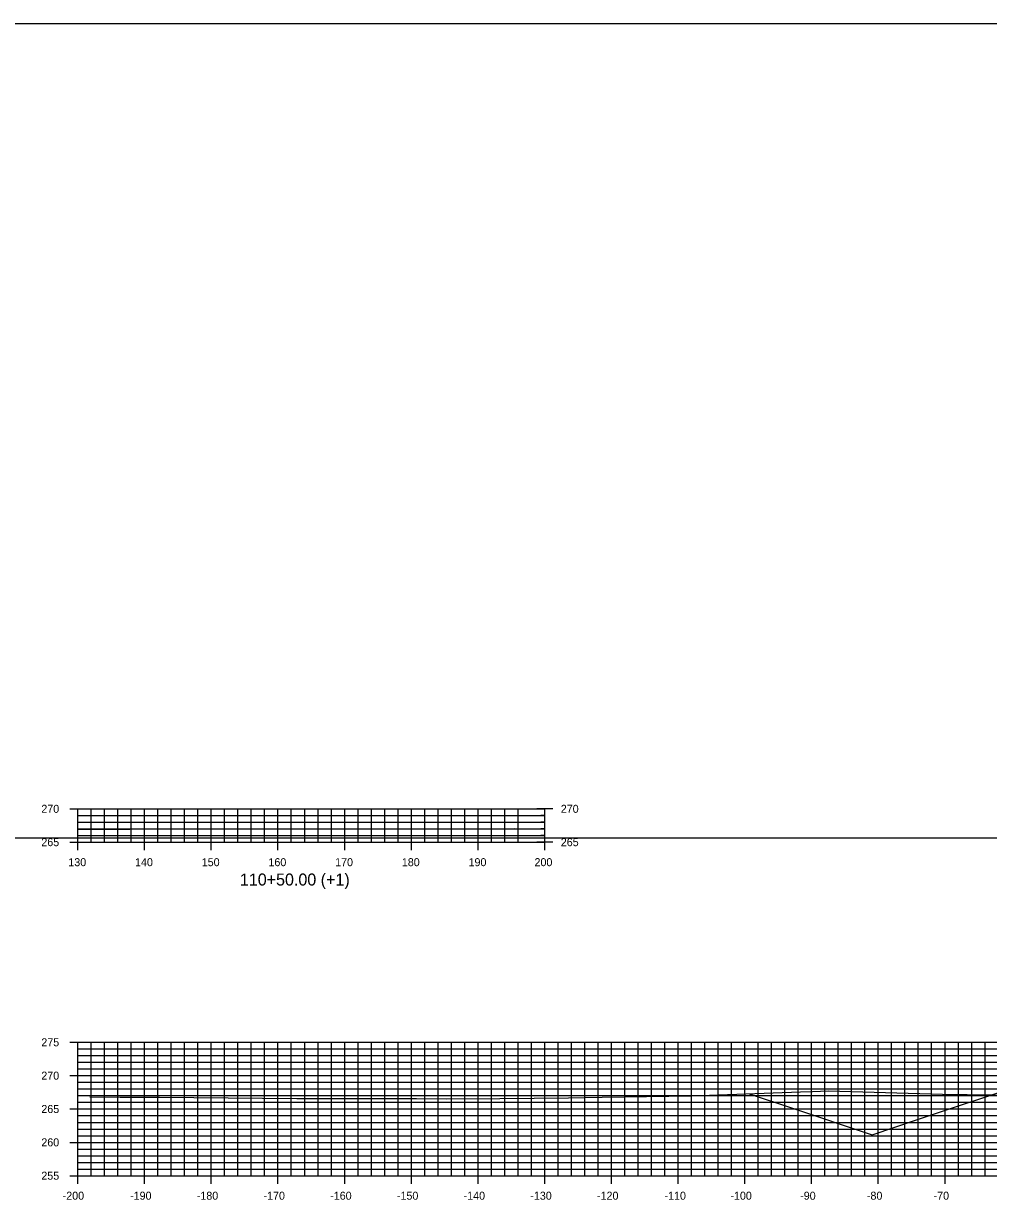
# Model space of a CAD drawing. Extents: x 1661012 to 1662122, y 670053 to 671852.
# Drawn here: x 1661778.9 to 1661923.5, y 671675 to 671852.4 of the extents above; entities that cross this region are included whole.
import ezdxf

# ---------------------------------------------------------------- set-up
doc = ezdxf.new("R2010")
doc.units = 0
for name, color, linetype in [('R_Concrete', 7, 'Continuous'), ('R_Concrete Hidden', 7, 'Continuous'), ('R_Erosion', 7, 'Continuous'), ('R_Exist Surface', 7, 'Continuous'), ('R_Proposed Road', 7, 'Continuous'), ('R_ROW Annot', 7, 'Continuous')]:
    doc.layers.add(name, color=color, linetype=linetype)

msp = doc.modelspace()

# ---------------------------------------------------------------- linework, layer by layer
at = {"layer": 'R_Concrete'}
for p, q in [((1661785.79, 671734.7), (1661788.19, 671734.7)), ((1661786.99, 671734.7), (1661856.99, 671734.7)), ((1661786.99, 671729.7), (1661786.99, 671734.7)), ((1661786.99, 671729.7), (1661786.99, 671734.7)), ((1661786.99, 671729.7), (1661786.99, 671734.7)), ((1661788.99, 671729.7), (1661788.99, 671734.7)), ((1661790.99, 671729.7), (1661790.99, 671734.7)), ((1661792.99, 671729.7), (1661792.99, 671734.7)), ((1661794.99, 671729.7), (1661794.99, 671734.7)), ((1661796.99, 671729.7), (1661796.99, 671734.7)), ((1661798.99, 671729.7), (1661798.99, 671734.7)), ((1661800.99, 671729.7), (1661800.99, 671734.7)), ((1661802.99, 671729.7), (1661802.99, 671734.7)), ((1661804.99, 671729.7), (1661804.99, 671734.7)), ((1661806.99, 671729.7), (1661806.99, 671734.7)), ((1661808.99, 671729.7), (1661808.99, 671734.7)), ((1661810.99, 671729.7), (1661810.99, 671734.7)), ((1661812.99, 671729.7), (1661812.99, 671734.7)), ((1661814.99, 671729.7), (1661814.99, 671734.7)), ((1661816.99, 671729.7), (1661816.99, 671734.7)), ((1661818.99, 671729.7), (1661818.99, 671734.7)), ((1661820.99, 671729.7), (1661820.99, 671734.7)), ((1661822.99, 671729.7), (1661822.99, 671734.7)), ((1661824.99, 671729.7), (1661824.99, 671734.7)), ((1661826.99, 671729.7), (1661826.99, 671734.7)), ((1661828.99, 671729.7), (1661828.99, 671734.7)), ((1661830.99, 671729.7), (1661830.99, 671734.7)), ((1661832.99, 671729.7), (1661832.99, 671734.7)), ((1661834.99, 671729.7), (1661834.99, 671734.7)), ((1661836.99, 671729.7), (1661836.99, 671734.7)), ((1661838.99, 671729.7), (1661838.99, 671734.7)), ((1661840.99, 671729.7), (1661840.99, 671734.7)), ((1661842.99, 671729.7), (1661842.99, 671734.7)), ((1661844.99, 671729.7), (1661844.99, 671734.7)), ((1661846.99, 671729.7), (1661846.99, 671734.7)), ((1661848.99, 671729.7), (1661848.99, 671734.7)), ((1661850.99, 671729.7), (1661850.99, 671734.7)), ((1661852.99, 671729.7), (1661852.99, 671734.7)), ((1661858.19, 671734.7), (1661855.79, 671734.7)), ((1661856.99, 671729.7), (1661856.99, 671734.7)), ((1661856.99, 671729.7), (1661856.99, 671734.7)), ((1661786.99, 671733.7), (1661856.99, 671733.7)), ((1661786.99, 671733.7), (1661787.59, 671733.7)), ((1661786.99, 671732.7), (1661856.99, 671732.7)), ((1661786.99, 671732.7), (1661787.59, 671732.7)), ((1661856.99, 671733.7), (1661856.39, 671733.7)), ((1661856.99, 671732.7), (1661856.39, 671732.7)), ((1661786.99, 671731.7), (1661856.99, 671731.7)), ((1661786.99, 671731.7), (1661787.59, 671731.7)), ((1661786.99, 671728.5), (1661786.99, 671730.9)), ((1661786.99, 671728.5), (1661786.99, 671730.9)), ((1661796.99, 671728.5), (1661796.99, 671730.9)), ((1661806.99, 671728.5), (1661806.99, 671730.9)), ((1661816.99, 671728.5), (1661816.99, 671730.9)), ((1661826.99, 671728.5), (1661826.99, 671730.9)), ((1661836.99, 671728.5), (1661836.99, 671730.9)), ((1661846.99, 671728.5), (1661846.99, 671730.9)), ((1661856.99, 671731.7), (1661856.39, 671731.7)), ((1661856.99, 671728.5), (1661856.99, 671730.9)), ((1661785.79, 671729.7), (1661788.19, 671729.7)), ((1661786.99, 671730.7), (1661856.99, 671730.7)), ((1661786.99, 671730.7), (1661787.59, 671730.7)), ((1661786.99, 671729.7), (1661786.99, 671730.3)), ((1661786.99, 671729.7), (1661856.99, 671729.7)), ((1661788.99, 671729.7), (1661788.99, 671730.3)), ((1661790.99, 671729.7), (1661790.99, 671730.3)), ((1661792.99, 671729.7), (1661792.99, 671730.3)), ((1661794.99, 671729.7), (1661794.99, 671730.3)), ((1661798.99, 671729.7), (1661798.99, 671730.3)), ((1661800.99, 671729.7), (1661800.99, 671730.3)), ((1661802.99, 671729.7), (1661802.99, 671730.3)), ((1661804.99, 671729.7), (1661804.99, 671730.3)), ((1661808.99, 671729.7), (1661808.99, 671730.3)), ((1661810.99, 671729.7), (1661810.99, 671730.3)), ((1661812.99, 671729.7), (1661812.99, 671730.3)), ((1661814.99, 671729.7), (1661814.99, 671730.3)), ((1661818.99, 671729.7), (1661818.99, 671730.3)), ((1661820.99, 671729.7), (1661820.99, 671730.3)), ((1661822.99, 671729.7), (1661822.99, 671730.3)), ((1661824.99, 671729.7), (1661824.99, 671730.3)), ((1661828.99, 671729.7), (1661828.99, 671730.3)), ((1661830.99, 671729.7), (1661830.99, 671730.3)), ((1661832.99, 671729.7), (1661832.99, 671730.3)), ((1661834.99, 671729.7), (1661834.99, 671730.3)), ((1661838.99, 671729.7), (1661838.99, 671730.3)), ((1661840.99, 671729.7), (1661840.99, 671730.3)), ((1661842.99, 671729.7), (1661842.99, 671730.3)), ((1661844.99, 671729.7), (1661844.99, 671730.3)), ((1661848.99, 671729.7), (1661848.99, 671730.3)), ((1661850.99, 671729.7), (1661850.99, 671730.3)), ((1661852.99, 671729.7), (1661852.99, 671730.3)), ((1661858.19, 671729.7), (1661855.79, 671729.7)), ((1661856.99, 671730.7), (1661856.39, 671730.7)), ((1661856.99, 671729.7), (1661856.99, 671730.3)), ((1661785.79, 671699.7), (1661788.19, 671699.7)), ((1661786.99, 671699.7), (1662116.99, 671699.7)), ((1661786.99, 671679.7), (1661786.99, 671699.7)), ((1661788.99, 671679.7), (1661788.99, 671699.7)), ((1661790.99, 671679.7), (1661790.99, 671699.7)), ((1661792.99, 671679.7), (1661792.99, 671699.7)), ((1661794.99, 671679.7), (1661794.99, 671699.7)), ((1661796.99, 671679.7), (1661796.99, 671699.7)), ((1661798.99, 671679.7), (1661798.99, 671699.7)), ((1661800.99, 671679.7), (1661800.99, 671699.7)), ((1661802.99, 671679.7), (1661802.99, 671699.7)), ((1661804.99, 671679.7), (1661804.99, 671699.7)), ((1661806.99, 671679.7), (1661806.99, 671699.7)), ((1661808.99, 671679.7), (1661808.99, 671699.7)), ((1661810.99, 671679.7), (1661810.99, 671699.7)), ((1661812.99, 671679.7), (1661812.99, 671699.7)), ((1661814.99, 671679.7), (1661814.99, 671699.7)), ((1661816.99, 671679.7), (1661816.99, 671699.7)), ((1661818.99, 671679.7), (1661818.99, 671699.7)), ((1661820.99, 671679.7), (1661820.99, 671699.7)), ((1661822.99, 671679.7), (1661822.99, 671699.7)), ((1661824.99, 671679.7), (1661824.99, 671699.7)), ((1661826.99, 671679.7), (1661826.99, 671699.7)), ((1661828.99, 671679.7), (1661828.99, 671699.7)), ((1661830.99, 671679.7), (1661830.99, 671699.7)), ((1661832.99, 671679.7), (1661832.99, 671699.7)), ((1661834.99, 671679.7), (1661834.99, 671699.7)), ((1661836.99, 671679.7), (1661836.99, 671699.7)), ((1661838.99, 671679.7), (1661838.99, 671699.7)), ((1661840.99, 671679.7), (1661840.99, 671699.7)), ((1661842.99, 671679.7), (1661842.99, 671699.7)), ((1661844.99, 671679.7), (1661844.99, 671699.7)), ((1661846.99, 671679.7), (1661846.99, 671699.7)), ((1661848.99, 671679.7), (1661848.99, 671699.7)), ((1661850.99, 671679.7), (1661850.99, 671699.7)), ((1661852.99, 671679.7), (1661852.99, 671699.7)), ((1661854.99, 671679.7), (1661854.99, 671699.7)), ((1661856.99, 671679.7), (1661856.99, 671699.7)), ((1661858.99, 671679.7), (1661858.99, 671699.7)), ((1661860.99, 671679.7), (1661860.99, 671699.7)), ((1661862.99, 671679.7), (1661862.99, 671699.7)), ((1661864.99, 671679.7), (1661864.99, 671699.7)), ((1661866.99, 671679.7), (1661866.99, 671699.7)), ((1661868.99, 671679.7), (1661868.99, 671699.7)), ((1661870.99, 671679.7), (1661870.99, 671699.7)), ((1661872.99, 671679.7), (1661872.99, 671699.7)), ((1661874.99, 671679.7), (1661874.99, 671699.7)), ((1661876.99, 671679.7), (1661876.99, 671699.7)), ((1661878.99, 671679.7), (1661878.99, 671699.7)), ((1661880.99, 671679.7), (1661880.99, 671699.7)), ((1661882.99, 671679.7), (1661882.99, 671699.7)), ((1661884.99, 671679.7), (1661884.99, 671699.7)), ((1661886.99, 671679.7), (1661886.99, 671699.7)), ((1661888.99, 671679.7), (1661888.99, 671699.7)), ((1661890.99, 671679.7), (1661890.99, 671699.7)), ((1661892.99, 671679.7), (1661892.99, 671699.7)), ((1661894.99, 671679.7), (1661894.99, 671699.7)), ((1661896.99, 671679.7), (1661896.99, 671699.7)), ((1661898.99, 671679.7), (1661898.99, 671699.7)), ((1661900.99, 671679.7), (1661900.99, 671699.7)), ((1661902.99, 671679.7), (1661902.99, 671699.7)), ((1661904.99, 671679.7), (1661904.99, 671699.7)), ((1661906.99, 671679.7), (1661906.99, 671699.7)), ((1661908.99, 671679.7), (1661908.99, 671699.7)), ((1661910.99, 671679.7), (1661910.99, 671699.7)), ((1661912.99, 671679.7), (1661912.99, 671699.7)), ((1661914.99, 671679.7), (1661914.99, 671699.7)), ((1661916.99, 671679.7), (1661916.99, 671699.7)), ((1661918.99, 671679.7), (1661918.99, 671699.7)), ((1661920.99, 671679.7), (1661920.99, 671699.7)), ((1661922.99, 671679.7), (1661922.99, 671699.7)), ((1661786.99, 671698.7), (1662116.99, 671698.7)), ((1661786.99, 671698.7), (1661787.59, 671698.7)), ((1661786.99, 671697.7), (1662116.99, 671697.7)), ((1661786.99, 671697.7), (1661787.59, 671697.7)), ((1661786.99, 671696.7), (1662116.99, 671696.7)), ((1661786.99, 671696.7), (1661787.59, 671696.7)), ((1661786.99, 671695.7), (1662116.99, 671695.7)), ((1661786.99, 671695.7), (1661787.59, 671695.7)), ((1661785.79, 671694.7), (1661788.19, 671694.7)), ((1661786.99, 671694.7), (1662116.99, 671694.7)), ((1661786.99, 671693.7), (1662116.99, 671693.7)), ((1661786.99, 671693.7), (1661787.59, 671693.7)), ((1661786.99, 671692.7), (1662116.99, 671692.7)), ((1661786.99, 671692.7), (1661787.59, 671692.7)), ((1661786.99, 671691.7), (1662116.99, 671691.7)), ((1661786.99, 671691.7), (1661787.59, 671691.7)), ((1661786.99, 671690.7), (1662116.99, 671690.7)), ((1661786.99, 671690.7), (1661787.59, 671690.7)), ((1661785.79, 671689.7), (1661788.19, 671689.7)), ((1661786.99, 671689.7), (1662116.99, 671689.7)), ((1661786.99, 671688.7), (1662116.99, 671688.7)), ((1661786.99, 671688.7), (1661787.59, 671688.7)), ((1661786.99, 671687.7), (1662116.99, 671687.7)), ((1661786.99, 671687.7), (1661787.59, 671687.7)), ((1661786.99, 671686.7), (1662116.99, 671686.7)), ((1661786.99, 671686.7), (1661787.59, 671686.7)), ((1661786.99, 671685.7), (1662116.99, 671685.7)), ((1661786.99, 671685.7), (1661787.59, 671685.7)), ((1661785.79, 671684.7), (1661788.19, 671684.7)), ((1661786.99, 671684.7), (1662116.99, 671684.7)), ((1661786.99, 671683.7), (1662116.99, 671683.7)), ((1661786.99, 671683.7), (1661787.59, 671683.7)), ((1661786.99, 671682.7), (1662116.99, 671682.7)), ((1661786.99, 671682.7), (1661787.59, 671682.7)), ((1661786.99, 671681.7), (1662116.99, 671681.7)), ((1661786.99, 671681.7), (1661787.59, 671681.7)), ((1661785.79, 671679.7), (1661788.19, 671679.7)), ((1661786.99, 671678.5), (1661786.99, 671680.9)), ((1661786.99, 671680.7), (1662116.99, 671680.7)), ((1661786.99, 671680.7), (1661787.59, 671680.7)), ((1661786.99, 671679.7), (1662116.99, 671679.7)), ((1661788.99, 671679.7), (1661788.99, 671680.3)), ((1661790.99, 671679.7), (1661790.99, 671680.3)), ((1661792.99, 671679.7), (1661792.99, 671680.3)), ((1661794.99, 671679.7), (1661794.99, 671680.3)), ((1661796.99, 671678.5), (1661796.99, 671680.9)), ((1661798.99, 671679.7), (1661798.99, 671680.3)), ((1661800.99, 671679.7), (1661800.99, 671680.3)), ((1661802.99, 671679.7), (1661802.99, 671680.3)), ((1661804.99, 671679.7), (1661804.99, 671680.3)), ((1661806.99, 671678.5), (1661806.99, 671680.9)), ((1661808.99, 671679.7), (1661808.99, 671680.3)), ((1661810.99, 671679.7), (1661810.99, 671680.3)), ((1661812.99, 671679.7), (1661812.99, 671680.3)), ((1661814.99, 671679.7), (1661814.99, 671680.3)), ((1661816.99, 671678.5), (1661816.99, 671680.9)), ((1661818.99, 671679.7), (1661818.99, 671680.3)), ((1661820.99, 671679.7), (1661820.99, 671680.3)), ((1661822.99, 671679.7), (1661822.99, 671680.3)), ((1661824.99, 671679.7), (1661824.99, 671680.3)), ((1661826.99, 671678.5), (1661826.99, 671680.9)), ((1661828.99, 671679.7), (1661828.99, 671680.3)), ((1661830.99, 671679.7), (1661830.99, 671680.3)), ((1661832.99, 671679.7), (1661832.99, 671680.3)), ((1661834.99, 671679.7), (1661834.99, 671680.3)), ((1661836.99, 671678.5), (1661836.99, 671680.9)), ((1661838.99, 671679.7), (1661838.99, 671680.3)), ((1661840.99, 671679.7), (1661840.99, 671680.3)), ((1661842.99, 671679.7), (1661842.99, 671680.3)), ((1661844.99, 671679.7), (1661844.99, 671680.3)), ((1661846.99, 671678.5), (1661846.99, 671680.9)), ((1661848.99, 671679.7), (1661848.99, 671680.3)), ((1661850.99, 671679.7), (1661850.99, 671680.3)), ((1661852.99, 671679.7), (1661852.99, 671680.3)), ((1661854.99, 671679.7), (1661854.99, 671680.3)), ((1661856.99, 671678.5), (1661856.99, 671680.9)), ((1661858.99, 671679.7), (1661858.99, 671680.3)), ((1661860.99, 671679.7), (1661860.99, 671680.3)), ((1661862.99, 671679.7), (1661862.99, 671680.3)), ((1661864.99, 671679.7), (1661864.99, 671680.3)), ((1661866.99, 671678.5), (1661866.99, 671680.9)), ((1661868.99, 671679.7), (1661868.99, 671680.3)), ((1661870.99, 671679.7), (1661870.99, 671680.3)), ((1661872.99, 671679.7), (1661872.99, 671680.3)), ((1661874.99, 671679.7), (1661874.99, 671680.3)), ((1661876.99, 671678.5), (1661876.99, 671680.9)), ((1661878.99, 671679.7), (1661878.99, 671680.3)), ((1661880.99, 671679.7), (1661880.99, 671680.3)), ((1661882.99, 671679.7), (1661882.99, 671680.3)), ((1661884.99, 671679.7), (1661884.99, 671680.3)), ((1661886.99, 671678.5), (1661886.99, 671680.9)), ((1661888.99, 671679.7), (1661888.99, 671680.3)), ((1661890.99, 671679.7), (1661890.99, 671680.3)), ((1661892.99, 671679.7), (1661892.99, 671680.3)), ((1661894.99, 671679.7), (1661894.99, 671680.3)), ((1661896.99, 671678.5), (1661896.99, 671680.9)), ((1661898.99, 671679.7), (1661898.99, 671680.3)), ((1661900.99, 671679.7), (1661900.99, 671680.3)), ((1661902.99, 671679.7), (1661902.99, 671680.3)), ((1661904.99, 671679.7), (1661904.99, 671680.3)), ((1661906.99, 671678.5), (1661906.99, 671680.9)), ((1661908.99, 671679.7), (1661908.99, 671680.3)), ((1661910.99, 671679.7), (1661910.99, 671680.3)), ((1661912.99, 671679.7), (1661912.99, 671680.3)), ((1661914.99, 671679.7), (1661914.99, 671680.3)), ((1661916.99, 671678.5), (1661916.99, 671680.9)), ((1661918.99, 671679.7), (1661918.99, 671680.3)), ((1661920.99, 671679.7), (1661920.99, 671680.3)), ((1661922.99, 671679.7), (1661922.99, 671680.3))]:
    msp.add_line(p, q, dxfattribs=at)
at = {"layer": 'R_Erosion'}
for points in [[(1661786.99, 671731.65), (1661794.77, 671731.67), (1661803.85, 671731.69), (1661809.99, 671731.7), (1661824.14, 671731.71), (1661824.66, 671731.71), (1661825.93, 671731.71), (1661827.34, 671731.71), (1661852.47, 671731.73), (1661854.38, 671731.71), (1661856.52, 671731.69), (1661856.99, 671731.69)], [(1661788.8, 671691.51), (1661793.31, 671691.48), (1661795.03, 671691.47), (1661799.25, 671691.45), (1661819.81, 671691.29), (1661837.77, 671691.27), (1661842.27, 671691.24), (1661850.27, 671691.25), (1661860.54, 671691.35), (1661865.58, 671691.48), (1661878.93, 671691.69), (1661895.33, 671692.26), (1661897.12, 671692.3), (1661899.5, 671692.4), (1661916.6, 671691.92), (1661927.74, 671691.76)]]:
    msp.add_lwpolyline(points, dxfattribs=at)
at = {"layer": 'R_Exist Surface'}
for p, q in [((1661786.99, 671729.7), (1661786.99, 671734.7)), ((1661856.99, 671729.7), (1661856.99, 671734.7)), ((1661786.99, 671729.7), (1661856.99, 671729.7)), ((1661786.99, 671679.7), (1661786.99, 671699.7)), ((1661786.99, 671679.7), (1662116.99, 671679.7))]:
    msp.add_line(p, q, dxfattribs=at)
at = {"layer": 'R_Proposed Road'}
for points in [[(1661756.99, 671659.7), (1662116.99, 671659.7), (1662116.99, 671852.4), (1661756.99, 671852.4)], [(1661677.02, 671537.62), (1662037.02, 671537.62), (1662037.02, 671730.32), (1661677.02, 671730.32)]]:
    msp.add_lwpolyline(points, close=True, dxfattribs=at)
at = {"layer": 'R_ROW Annot'}
msp.add_lwpolyline([(1661887.61, 671691.99), (1661894.14, 671689.81), (1661906.05, 671685.85), (1661912.74, 671688.08), (1661928.67, 671693.39), (1661930, 671693.83), (1661934.7, 671695.39), (1661935.49, 671695.66), (1661938.67, 671696.72), (1661939.04, 671696.71), (1661940.67, 671696.68), (1661942.4, 671696.61), (1661950.67, 671696.29), (1661959.78, 671695.93), (1661960.67, 671695.89), (1661962.52, 671695.82), (1661962.67, 671695.81), (1661966.39, 671694.57), (1661966.63, 671694.49), (1661972.49, 671692.54), (1661972.67, 671692.48), (1661973.2, 671692.31), (1661978.44, 671690.56), (1661990.76, 671686.45)], dxfattribs=at)

# ---------------------------------------------------------------- texts
at = {"layer": 'R_Concrete Hidden'}
for s, height, p in [('270', 1.2, (1661781.51, 671734.1)), ('270', 1.2, (1661859.39, 671734.1)), ('265', 1.2, (1661781.51, 671729.1)), ('265', 1.2, (1661859.39, 671729.1)), ('130', 1.2, (1661785.56, 671726.1)), ('130', 1.2, (1661785.56, 671726.1)), ('140', 1.2, (1661795.56, 671726.1)), ('150', 1.2, (1661805.56, 671726.1)), ('160', 1.2, (1661815.56, 671726.1)), ('170', 1.2, (1661825.56, 671726.1)), ('180', 1.2, (1661835.56, 671726.1)), ('190', 1.2, (1661845.56, 671726.1)), ('200', 1.2, (1661855.45, 671726.1)), ('110+50.00 (+1)', 1.8, (1661811.28, 671723.2)), ('275', 1.2, (1661781.51, 671699.1)), ('270', 1.2, (1661781.51, 671694.1)), ('265', 1.2, (1661781.51, 671689.1)), ('260', 1.2, (1661781.51, 671684.1)), ('255', 1.2, (1661781.51, 671679.1)), ('-200', 1.2, (1661784.71, 671676.1)), ('-190', 1.2, (1661794.82, 671676.1)), ('-180', 1.2, (1661804.82, 671676.1)), ('-170', 1.2, (1661814.82, 671676.1)), ('-160', 1.2, (1661824.82, 671676.1)), ('-150', 1.2, (1661834.82, 671676.1)), ('-140', 1.2, (1661844.82, 671676.1)), ('-130', 1.2, (1661854.82, 671676.1)), ('-120', 1.2, (1661864.82, 671676.1)), ('-110', 1.2, (1661874.94, 671676.1)), ('-100', 1.2, (1661884.82, 671676.1)), ('-90', 1.2, (1661895.28, 671676.1)), ('-80', 1.2, (1661905.28, 671676.1)), ('-70', 1.2, (1661915.28, 671676.1))]:
    msp.add_text(s, height=height, dxfattribs=at).set_placement(p)
at = {"layer": 'R_Exist Surface'}
for p in [(1661786.99, 671729.7), (1661786.99, 671679.7)]:
    msp.add_text('-', height=0.0001, dxfattribs=at).set_placement(p)

doc.saveas('drawing.dxf')
